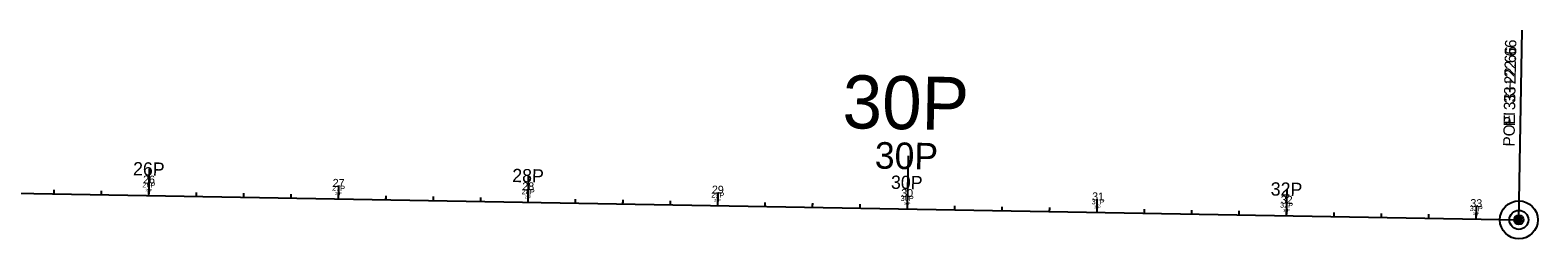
# Model space of a CAD drawing. Extents: x 564646 to 607088, y 225853 to 261760.
# Drawn here: x 599207 to 600002, y 244317 to 244427 of the extents above; entities that cross this region are included whole.
import ezdxf

# ---------------------------------------------------------------- set-up
doc = ezdxf.new("R2010")
doc.units = 0
for name, color, linetype in [('B_CONC_HIDDEN_LT', 7, 'Continuous'), ('B_CONST', 7, 'Continuous'), ('B_EXIST', 7, 'Continuous'), ('B_TEXT', 7, 'Continuous'), ('E-Easements', 7, 'Continuous'), ('E-Property Lines', 7, 'Continuous'), ('E_ALI_100', 7, 'Continuous'), ('E_RW_CorporateLimits', 7, 'Continuous'), ('E_RW_EasementUtility_Text', 7, 'Continuous'), ('E_WTR_FlowLine', 7, 'Continuous'), ('EMCS_SURVEY_PT CODES', 7, 'Continuous'), ('EMCS_SURVEY_PT ELEV', 7, 'Continuous'), ('EMCS_SURVEY_PT NOTES', 7, 'Continuous'), ('Level 33', 7, 'Continuous'), ('P-Easements Floodplain', 7, 'Continuous'), ('P-Easements Temporary', 7, 'Continuous'), ('P_ALI_100_Tic', 7, 'Continuous'), ('P_ALI_20', 7, 'Continuous'), ('P_ALI_50', 7, 'Continuous'), ('P_RW_EasementPerm', 7, 'Continuous'), ('P_RW_EasementTemp', 7, 'Continuous'), ('P_RW_PropertyConnector', 7, 'Continuous'), ('P_RW_Proposed', 7, 'Continuous'), ('P_WAL', 7, 'Continuous')]:
    doc.layers.add(name, color=color, linetype=linetype)

msp = doc.modelspace()

# ---------------------------------------------------------------- linework, layer by layer
at = {"layer": 'B_CONC_HIDDEN_LT'}
msp.add_line((597331.47, 244374.38), (599991.86, 244327.13), dxfattribs=at)
at = {"layer": 'B_CONST'}
msp.add_circle((599991.86, 244327.13), 1.5, dxfattribs=at)
msp.add_circle((599991.86, 244327.13), 1.5, dxfattribs=at)
at = {"layer": 'B_EXIST'}
msp.add_circle((599991.86, 244327.13), 5, dxfattribs=at)
at = {"layer": 'B_TEXT'}
msp.add_lwpolyline([(599991.86, 244327.13), (599993.64, 244427.11)], dxfattribs=at)
at = {"layer": 'E-Easements'}
msp.add_circle((599991.86, 244327.13), 2.5, dxfattribs=at)
at = {"layer": 'E_ALI_100'}
for points in [[(599219.35, 244342.25), (599219.32, 244340.85)], [(599244.35, 244341.81), (599244.32, 244340.41)], [(599269.37, 244342.76), (599269.32, 244339.96)], [(599294.34, 244340.92), (599294.31, 244339.52)], [(599319.33, 244340.47), (599319.31, 244339.07)], [(599344.33, 244340.03), (599344.3, 244338.63)], [(599369.35, 244340.99), (599369.3, 244338.19)], [(599394.32, 244339.14), (599394.3, 244337.74)], [(599419.32, 244338.7), (599419.29, 244337.3)], [(599444.31, 244338.25), (599444.29, 244336.86)], [(599469.33, 244339.21), (599469.29, 244336.41)], [(599494.31, 244337.37), (599494.28, 244335.97)], [(599519.3, 244336.92), (599519.28, 244335.52)], [(599544.3, 244336.48), (599544.27, 244335.08)], [(599569.32, 244337.44), (599569.27, 244334.64)], [(599594.29, 244335.59), (599594.27, 244334.19)], [(599619.29, 244335.15), (599619.26, 244333.75)], [(599644.28, 244334.7), (599644.26, 244333.3)], [(599669.3, 244335.66), (599669.25, 244332.86)], [(599694.27, 244333.82), (599694.25, 244332.42)], [(599719.27, 244333.37), (599719.25, 244331.97)], [(599744.27, 244332.93), (599744.24, 244331.53)], [(599769.29, 244333.88), (599769.24, 244331.08)], [(599794.26, 244332.04), (599794.23, 244330.64)], [(599869.27, 244332.11), (599869.22, 244329.31)], [(599819.25, 244331.6), (599819.23, 244330.2)], [(599844.25, 244331.15), (599844.23, 244329.75)], [(599894.24, 244330.26), (599894.22, 244328.86)], [(599919.24, 244329.82), (599919.21, 244328.42)], [(599944.24, 244329.38), (599944.21, 244327.98)], [(599969.26, 244330.33), (599969.21, 244327.53)]]:
    msp.add_lwpolyline(points, dxfattribs=at)
at = {"layer": 'E_WTR_FlowLine'}
msp.add_circle((599991.86, 244327.13), 0.5, dxfattribs=at)
at = {"layer": 'EMCS_SURVEY_PT CODES'}
msp.add_line((597331.47, 244374.38), (599991.86, 244327.13), dxfattribs=at)
at = {"layer": 'EMCS_SURVEY_PT ELEV'}
msp.add_line((597331.47, 244374.38), (599991.86, 244327.13), dxfattribs=at)
msp.add_line((597331.47, 244374.38), (599991.86, 244327.13), dxfattribs=at)
at = {"layer": 'EMCS_SURVEY_PT NOTES'}
for points in [[(599219.36, 244342.95), (599219.32, 244340.85)], [(599244.36, 244342.51), (599244.32, 244340.41)], [(599269.39, 244344.16), (599269.32, 244339.96)], [(599294.35, 244341.62), (599294.31, 244339.52)], [(599319.35, 244341.17), (599319.31, 244339.07)], [(599344.34, 244340.73), (599344.3, 244338.63)], [(599369.38, 244342.39), (599369.3, 244338.19)], [(599469.36, 244340.61), (599469.29, 244336.41)], [(599394.33, 244339.84), (599394.3, 244337.74)], [(599419.33, 244339.4), (599419.29, 244337.3)], [(599444.33, 244338.95), (599444.29, 244336.86)], [(599494.32, 244338.07), (599494.28, 244335.97)], [(599519.31, 244337.62), (599519.28, 244335.52)], [(599544.31, 244337.18), (599544.27, 244335.08)], [(599569.34, 244338.83), (599569.27, 244334.64)], [(599594.3, 244336.29), (599594.27, 244334.19)], [(599619.3, 244335.85), (599619.26, 244333.75)], [(599644.29, 244335.4), (599644.26, 244333.3)], [(599669.33, 244337.06), (599669.25, 244332.86)], [(599694.29, 244334.52), (599694.25, 244332.42)], [(599719.28, 244334.07), (599719.25, 244331.97)], [(599744.28, 244333.63), (599744.24, 244331.53)], [(599769.31, 244335.28), (599769.24, 244331.08)], [(599794.27, 244332.74), (599794.23, 244330.64)], [(599819.27, 244332.3), (599819.23, 244330.2)], [(599869.3, 244333.51), (599869.22, 244329.31)], [(599844.26, 244331.85), (599844.23, 244329.75)], [(599894.26, 244330.96), (599894.22, 244328.86)], [(599919.25, 244330.52), (599919.21, 244328.42)], [(599944.25, 244330.08), (599944.21, 244327.98)], [(599969.28, 244331.73), (599969.21, 244327.53)]]:
    msp.add_lwpolyline(points, dxfattribs=at)
at = {"layer": 'Level 33'}
for points in [[(599219.34, 244341.55), (599219.32, 244340.85)], [(599244.33, 244341.11), (599244.32, 244340.41)], [(599269.34, 244341.36), (599269.32, 244339.96)], [(599294.33, 244340.22), (599294.31, 244339.52)], [(599319.32, 244339.77), (599319.31, 244339.07)], [(599344.32, 244339.33), (599344.3, 244338.63)], [(599369.33, 244339.59), (599369.3, 244338.19)], [(599394.31, 244338.44), (599394.3, 244337.74)], [(599419.31, 244338), (599419.29, 244337.3)], [(599444.3, 244337.56), (599444.29, 244336.86)], [(599469.31, 244337.81), (599469.29, 244336.41)], [(599494.29, 244336.67), (599494.28, 244335.97)], [(599519.29, 244336.22), (599519.28, 244335.52)], [(599544.29, 244335.78), (599544.27, 244335.08)], [(599569.29, 244336.04), (599569.27, 244334.64)], [(599594.28, 244334.89), (599594.27, 244334.19)], [(599619.27, 244334.45), (599619.26, 244333.75)], [(599644.27, 244334), (599644.26, 244333.3)], [(599669.28, 244334.26), (599669.25, 244332.86)], [(599694.26, 244333.12), (599694.25, 244332.42)], [(599719.26, 244332.67), (599719.25, 244331.97)], [(599744.25, 244332.23), (599744.24, 244331.53)], [(599769.26, 244332.48), (599769.24, 244331.08)], [(599794.25, 244331.34), (599794.23, 244330.64)], [(599819.24, 244330.9), (599819.23, 244330.2)], [(599844.24, 244330.45), (599844.23, 244329.75)], [(599869.25, 244330.71), (599869.22, 244329.31)], [(599894.23, 244329.56), (599894.22, 244328.86)], [(599919.23, 244329.12), (599919.21, 244328.42)], [(599944.22, 244328.68), (599944.21, 244327.98)], [(599969.23, 244328.93), (599969.21, 244327.53)]]:
    msp.add_lwpolyline(points, dxfattribs=at)
at = {"layer": 'P-Easements Floodplain'}
msp.add_line((597331.47, 244374.38), (599991.86, 244327.13), dxfattribs=at)
at = {"layer": 'P-Easements Temporary'}
msp.add_circle((599991.86, 244327.13), 10, dxfattribs=at)
at = {"layer": 'P_ALI_100_Tic'}
for points in [[(599669.75, 244360.86), (599669.25, 244332.86)], [(599269.57, 244353.96), (599269.32, 244339.96)], [(599469.53, 244350.41), (599469.29, 244336.41)], [(599869.47, 244343.31), (599869.22, 244329.31)]]:
    msp.add_lwpolyline(points, dxfattribs=at)
at = {"layer": 'P_ALI_20'}
for points in [[(599269.44, 244346.96), (599269.32, 244339.96)], [(599369.43, 244345.19), (599369.3, 244338.19)], [(599469.41, 244343.41), (599469.29, 244336.41)], [(599569.39, 244341.63), (599569.27, 244334.64)], [(599669.5, 244346.86), (599669.25, 244332.86)], [(599769.36, 244338.08), (599769.24, 244331.08)], [(599869.35, 244336.31), (599869.22, 244329.31)], [(599969.33, 244334.53), (599969.21, 244327.53)]]:
    msp.add_lwpolyline(points, dxfattribs=at)
at = {"layer": 'P_ALI_50'}
msp.add_lwpolyline([(599991.86, 244327.13), (599993.64, 244427.11)], dxfattribs=at)
at = {"layer": 'P_RW_EasementPerm'}
for points in [[(599269.44, 244346.96), (599269.32, 244339.96)], [(599369.36, 244341.69), (599369.3, 244338.19)], [(599469.41, 244343.41), (599469.29, 244336.41)], [(599669.38, 244339.86), (599669.25, 244332.86)], [(599569.33, 244338.13), (599569.27, 244334.64)], [(599769.3, 244334.58), (599769.24, 244331.08)], [(599869.35, 244336.31), (599869.22, 244329.31)], [(599969.27, 244331.03), (599969.21, 244327.53)]]:
    msp.add_lwpolyline(points, dxfattribs=at)
at = {"layer": 'P_RW_EasementTemp'}
msp.add_line((597331.47, 244374.38), (599991.86, 244327.13), dxfattribs=at)
at = {"layer": 'P_RW_PropertyConnector'}
msp.add_line((597331.47, 244374.38), (599991.86, 244327.13), dxfattribs=at)
at = {"layer": 'P_WAL'}
msp.add_circle((599991.86, 244327.13), 1, dxfattribs=at)

# ---------------------------------------------------------------- texts
for s, p in [('26P', (599266.01, 244344.22)), ('27P', (599365.99, 244342.45)), ('28P', (599465.98, 244340.67)), ('29P', (599565.94, 244338.9)), ('30P', (599665.83, 244337.12)), ('31P', (599766.5, 244335.33)), ('32P', (599865.91, 244333.57)), ('33P', (599965.9, 244331.79))]:
    msp.add_text(s, height=2.8, rotation=358.9825).set_placement(p)
at = {"layer": 'B_TEXT'}
msp.add_text('POE 33+22.66', height=6, rotation=88.9825, dxfattribs=at).set_placement((599989.55, 244365.76))
at = {"layer": 'E-Property Lines'}
msp.add_text('30P', height=28, rotation=358.9825, dxfattribs=at).set_placement((599635.06, 244375.47))
at = {"layer": 'E_RW_CorporateLimits'}
msp.add_text('30P', height=14, rotation=358.9825, dxfattribs=at).set_placement((599652.16, 244354.17))
at = {"layer": 'E_RW_EasementUtility_Text'}
for s, p in [('26P', (599267.66, 244342.09)), ('27P', (599367.65, 244340.32)), ('28P', (599467.63, 244338.54)), ('29P', (599567.6, 244336.77)), ('30P', (599667.54, 244334.99)), ('31P', (599767.87, 244333.21)), ('32P', (599867.57, 244331.44)), ('33P', (599967.55, 244329.66))]:
    msp.add_text(s, height=1.4, rotation=358.9825, dxfattribs=at).set_placement(p)
at = {"layer": 'EMCS_SURVEY_PT NOTES'}
for s, p in [('26', (599266.35, 244346.32)), ('27', (599366.34, 244344.54)), ('28', (599466.32, 244342.76)), ('29', (599566.31, 244340.99)), ('30', (599666.11, 244339.22)), ('31', (599766.8, 244337.43)), ('32', (599866.26, 244335.66)), ('33', (599966.24, 244333.89))]:
    msp.add_text(s, height=4.2, rotation=358.9825, dxfattribs=at).set_placement(p)
at = {"layer": 'P_ALI_50'}
msp.add_text('PI  33+22.66', height=6, rotation=88.9825, dxfattribs=at).set_placement((599989.74, 244376.44))
at = {"layer": 'P_RW_Proposed'}
for s, p in [('26P', (599261.04, 244350.61)), ('28P', (599461.01, 244347.06)), ('30P', (599660.71, 244343.51)), ('32P', (599860.95, 244339.96))]:
    msp.add_text(s, height=7, rotation=358.9825, dxfattribs=at).set_placement(p)

doc.saveas('drawing.dxf')
